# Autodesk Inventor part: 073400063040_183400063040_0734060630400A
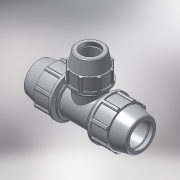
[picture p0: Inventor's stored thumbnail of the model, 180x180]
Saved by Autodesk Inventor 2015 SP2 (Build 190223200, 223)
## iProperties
Created: 2017-02
Part Number: 073400063040_183400063040_0734060630400A
Material: PVC-Piping
Description: PLASSON REDUCING TEE 63-40-63
Document SubType Name: Modeling
Designer: KIM
Mass: 92.6774 g
Surface Area: 199.44 cm^2
Volume: 66.1981 cm^3
Density: 1.4 g/cm^3
Appearance: Smooth - White
Author: Кирилл
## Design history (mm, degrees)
derived "07340.ipt"
feature "Solid1::07340.ipt"
feature "Solid2::07340.ipt"
tag "TaggingFeature1"
body "Solid1"
other parameters: "d2" = 63, "d4" = 11.16667, "d5" = 37.52, "d7" = 113, "d11" = 4.46667, "d13" = 120 deg, "d14" = 81.9, "d15" = 12 deg, "d16" = 98.31, "d18" = 3.15, "d19" = 35 deg, "d20" = 17.5 deg, "d21" = 105.09, "d23" = 0, "d25" = 360 deg, "d27" = 2.26, "d33" = 1.26, "d42" = 48.24, "d43" = 3.39, "d46" = 1.89, "d67" = 84.75, "d77" = 82, "d78" = 12 deg, "d79" = 139, "d80" = 120 deg, "d81" = 56, "d82" = 11.58333, "d87" = 4.63333, "d89" = 34.75, "d90" = 41.7, "d96" = 22.33333, "d98" = 76.26, "d99" = 35 deg, "d100" = 17.5 deg, "d102" = 0, "d103" = 1.64, "d107" = 360 deg, "d109" = 1.2, "d112" = 2, "d113" = 5.46667, "d114" = 0, "d117" = 268, "d118" = 71.34, "d126" = 56.7, "d127" = 113, "d131" = 5.56, "d132" = 36, "d133" = 84, "d135" = 0, "d138" = 5.36, "d143" = 0, "d148" = 61.5, "d168" = 56.7, "d170" = 0, "d173" = 0, "d175" = 0, "d176" = 5.46667, "d177" = 0, "d_" = 63, "E_" = 113, "A_" = 139, "l_" = 113, "E_1" = 82, "l_1" = 84, "H_" = 268
